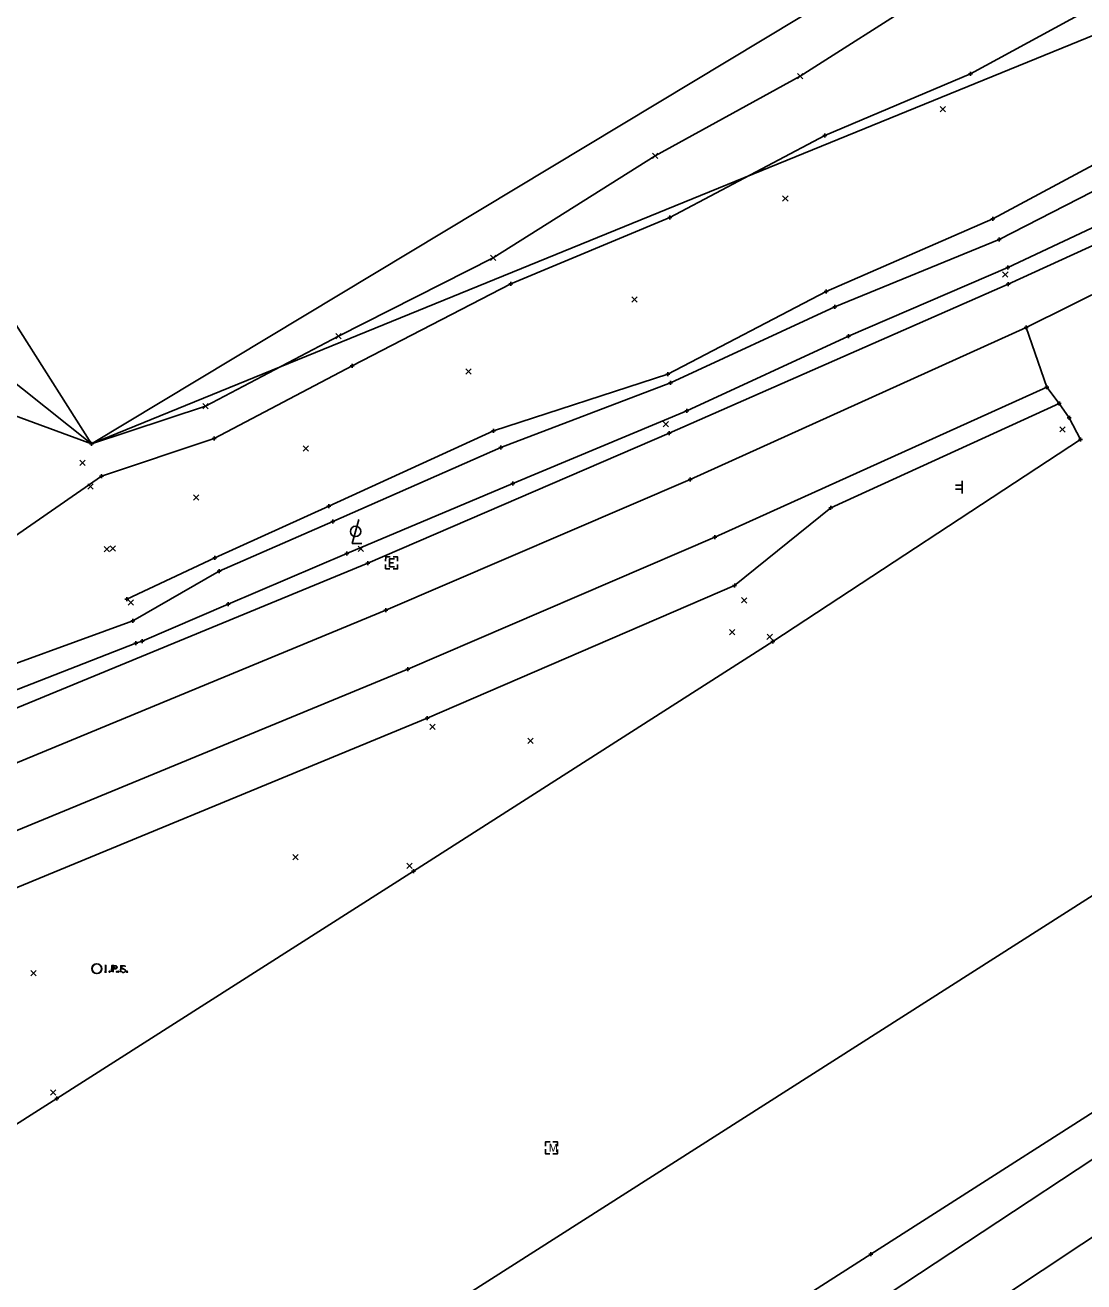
# Model space of a CAD drawing. Extents: x 142461 to 147261, y 511126 to 514697.
# Drawn here: x 145873.8 to 146138.4, y 513841.1 to 514155.2 of the extents above; entities that cross this region are included whole.
import ezdxf

# ---------------------------------------------------------------- set-up
doc = ezdxf.new("R2010")
doc.units = 0
for name, color, linetype in [('DR_X_Ditch', 7, 'Continuous'), ('DR_X_Storm_Sewer', 7, 'Continuous'), ('LT_X_Poles', 7, 'Continuous'), ('PM_X_Surveyed_Line', 7, 'Continuous'), ('PV_X_EOP', 7, 'Continuous'), ('RD_X_Fence', 7, 'Continuous'), ('SN_X_Public', 7, 'Continuous'), ('SV_P_Mon_Cells_Set', 7, 'Continuous'), ('SV_X_Mon_Cells_Found', 7, 'Continuous'), ('SV_X_Original_Ground', 7, 'Continuous'), ('SV_X_Random_Point', 7, 'Continuous'), ('SV_X_Shot_Marker', 7, 'Continuous'), ('SV_X_Toe_of_Slope', 7, 'Continuous'), ('SV_X_Top_of_Bank', 7, 'Continuous'), ('UT_X_Electric_Cells', 7, 'Continuous'), ('VG_X_Tree_Line_Lt', 7, 'Continuous')]:
    doc.layers.add(name, color=color, linetype=linetype)

msp = doc.modelspace()

# ---------------------------------------------------------------- linework, layer by layer
at = {"layer": 'DR_X_Ditch'}
msp.add_lwpolyline([(146157.06, 514121.98), (146117.23, 514101.58), (146076.19, 514084.75), (146035.13, 514065.78), (145992.71, 514049.65), (145950.73, 514031.13), (145922.3, 514018.72), (145900.71, 514006.31), (145857.21, 513990.47), (145797.53, 513968.82), (145752.93, 513945.88), (145703.51, 513927.11), (145660.81, 513900.76), (145647.2, 513892.42)], dxfattribs=at)
at = {"layer": 'DR_X_Storm_Sewer'}
msp.add_line((146183.01, 513964.68), (145764.65, 513697.97), dxfattribs=at)
at = {"layer": 'LT_X_Poles'}
msp.add_lwpolyline([(145957.21, 514031.59), (145955.57, 514025.62), (145957.94, 514025.59)], dxfattribs=at)
msp.add_circle((145956.39, 514028.64), 1.3, dxfattribs=at)
at = {"layer": 'PM_X_Surveyed_Line'}
for points in [[(146936.5, 514545.38), (146901.96, 514523.88), (146817.16, 514475.05), (146691.97, 514405.14), (146614.79, 514358.5), (146537.21, 514310.98), (146456.62, 514262.43), (146373.73, 514213.61), (146290.32, 514166.13), (146211.14, 514122.87), (146123.97, 514079.6), (146039.98, 514041.62), (145963.95, 514008.93), (145842.42, 513958.73), (145748.84, 513919.85), (145682.8, 513887.45), (145618.56, 513849.17)], [(145298.44, 513626.69), (145354.36, 513662.3), (145438.7, 513716.14), (145519.08, 513767.31), (145596.03, 513816.21), (145627.23, 513836.01), (145690.35, 513873.88), (145755.45, 513905.52), (145849.22, 513944.68), (145969.45, 513994.2), (146046.19, 514027.21), (146129.15, 514064.67)], [(145307.75, 513247.77), (145337.8, 513273.35), (145402.01, 513328.15), (145492.27, 513403.98), (145551.47, 513453.67), (145589.5, 513485), (145652.45, 513535.43), (145708.49, 513578.45), (145823.05, 513660.55), (145922.26, 513727.29), (146005.91, 513782.8), (146089.52, 513838.01), (146168.07, 513889.83), (146245.86, 513941.57), (146299.38, 513977.14)], [(145071.95, 513203.81), (145158.73, 513259.05), (145217.02, 513295.98), (145277.61, 513334.31), (145360.24, 513386.81), (145456.59, 513448.28), (145523.93, 513491.08), (145564.47, 513516.91), (145634.3, 513561.26), (145696.38, 513600.68), (145817.65, 513677.73), (145914.61, 513739.23), (145999.16, 513793.04), (146085.16, 513848.04), (146162.9, 513897.7)], [(145321.53, 513222.56), (145353.45, 513259.97), (145411.74, 513315.95), (145502.86, 513392.29), (145560.91, 513440.87), (145599.98, 513473.12), (145662.14, 513522.91), (145718.75, 513566.31), (145832.41, 513647.03), (145931.14, 513713.4), (146014.31, 513768.75), (146098.5, 513824.38), (146177.34, 513876.68)]]:
    msp.add_lwpolyline(points, dxfattribs=at)
at = {"layer": 'PV_X_EOP'}
for p, q in [((146207.13, 514130.54), (146119.47, 514090.47)), ((146119.47, 514090.47), (146034.79, 514053.23)), ((146034.79, 514053.23), (145959.48, 514020.69)), ((145959.48, 514020.69), (145837.72, 513970.53))]:
    msp.add_line(p, q, dxfattribs=at)
msp.add_lwpolyline([(145537.78, 513667.71), (145623.97, 513722.57), (145710.71, 513777.95), (145799.7, 513834.74), (145881.69, 513886.93), (145970.86, 513943.75), (146060.64, 514001.13), (146137.55, 514051.63), (146134.78, 514057.05), (146132.28, 514060.58), (146075.14, 514034.52), (146051.13, 514015.12), (145974.31, 513981.98), (145855.11, 513932.79), (145759.64, 513893.27), (145691.31, 513860.37), (145635.49, 513829), (145602.1, 513807.83)], dxfattribs=at)
at = {"layer": 'RD_X_Fence'}
msp.add_lwpolyline([(146900.86, 514646.23), (146332.42, 514316.7), (145890.39, 514050.56), (145774.93, 514232.06), (145655.09, 514421.49), (144949.64, 513970.2), (144936.36, 513451.75), (144101.94, 512896.99), (144046.01, 512862.62), (143758.01, 512670.87), (143619.22, 512579.24), (143474.12, 512483.15), (143357.83, 512406.57), (143315.36, 512377.21)], dxfattribs=at)
at = {"layer": 'SN_X_Public'}
for p, q in [((146107.97, 514041.3), (146107.97, 514038.1)), ((146107.97, 514040.18), (146106.37, 514040.18)), ((146107.97, 514039.22), (146106.37, 514039.22)), ((146107.97, 514039.7), (146107.97, 514039.7))]:
    msp.add_line(p, q, dxfattribs=at)
at = {"layer": 'SV_P_Mon_Cells_Set'}
for p, q in [((145893.73, 513918.51), (145894.13, 513918.51)), ((145893.74, 513920.11), (145894.14, 513920.11)), ((145893.93, 513918.51), (145893.94, 513920.11)), ((145895.78, 513919.33), (145896.42, 513919.32)), ((145898.77, 513919.11), (145898.04, 513919.5))]:
    msp.add_line(p, q, dxfattribs=at)
msp.add_lwpolyline([(145895.77, 513918.49), (145895.78, 513920.09), (145896.43, 513920.09)], dxfattribs=at)
for centre, radius in [((145891.74, 513919.34), 1.2), ((145894.89, 513918.61), 0.14), ((145896.73, 513918.59), 0.14), ((145899.3, 513918.56), 0.14)]:
    msp.add_circle(centre, radius, dxfattribs=at)
for points in [[(145896.42, 513919.32), (145896.49, 513919.33), (145896.67, 513919.43), (145896.74, 513919.61), (145896.75, 513919.7), (145896.75, 513919.7), (145896.75, 513919.7)], [(145896.43, 513920.09), (145896.56, 513920.05), (145896.7, 513919.94), (145896.75, 513919.8), (145896.75, 513919.7)], [(145898.04, 513919.5), (145897.83, 513919.71), (145898.03, 513919.97), (145898.03, 513919.97), (145898.03, 513919.97)], [(145898.76, 513918.58), (145898.23, 513918.29), (145897.91, 513918.68), (145897.91, 513918.68)], [(145898.03, 513919.97), (145898.41, 513920.14), (145898.84, 513919.96), (145898.84, 513919.96), (145898.84, 513919.96)], [(145898.76, 513918.58), (145898.96, 513918.82), (145898.77, 513919.11), (145898.77, 513919.11), (145898.77, 513919.11)]]:
    msp.add_open_spline(points, degree=2, dxfattribs=at)
at = {"layer": 'SV_X_Mon_Cells_Found'}
for points in [[(145893.66, 513918.55), (145894.02, 513918.55)], [(145893.68, 513920.15), (145894.03, 513920.15)], [(145893.84, 513918.55), (145893.86, 513920.15)], [(145894.8, 513918.75), (145894.86, 513918.75), (145894.89, 513918.73), (145894.92, 513918.68), (145894.92, 513918.61), (145894.89, 513918.56), (145894.85, 513918.54), (145894.8, 513918.54), (145894.77, 513918.56), (145894.73, 513918.62), (145894.74, 513918.68), (145894.77, 513918.73), (145894.8, 513918.75)], [(145895.41, 513918.53), (145895.42, 513920.13), (145895.95, 513920.13), (145896.01, 513920.11), (145896.08, 513920.09), (145896.12, 513920.06), (145896.15, 513920.04), (145896.19, 513919.97), (145896.23, 513919.91), (145896.25, 513919.81), (145896.24, 513919.66), (145896.23, 513919.61), (145896.21, 513919.53), (145896.17, 513919.44), (145896.12, 513919.41), (145896.09, 513919.38), (145896.03, 513919.36), (145895.94, 513919.35), (145895.41, 513919.35)], [(145897.05, 513918.73), (145897.11, 513918.73), (145897.14, 513918.7), (145897.17, 513918.65), (145897.17, 513918.59), (145897.14, 513918.54), (145897.1, 513918.52), (145897.05, 513918.52), (145897.02, 513918.54), (145896.98, 513918.59), (145896.98, 513918.66), (145897.02, 513918.71), (145897.05, 513918.73)], [(145898.43, 513920.1), (145897.67, 513920.11), (145897.65, 513918.51)], [(145897.66, 513919.33), (145898.2, 513919.32)], [(145899.2, 513918.71), (145899.25, 513918.71), (145899.29, 513918.68), (145899.32, 513918.63), (145899.32, 513918.57), (145899.29, 513918.52), (145899.25, 513918.49), (145899.2, 513918.49), (145899.16, 513918.52), (145899.13, 513918.57), (145899.13, 513918.63), (145899.17, 513918.68), (145899.2, 513918.71)], [(146004.96, 513873.1), (146003.83, 513873.11), (146003.85, 513874.23)], [(146003.85, 513874.99), (146003.86, 513876.11), (146004.99, 513876.1)], [(146006.85, 513874.2), (146006.84, 513873.08), (146005.69, 513873.09)], [(146005.72, 513876.09), (146006.87, 513876.08), (146006.85, 513874.96)]]:
    msp.add_lwpolyline(points, dxfattribs=at)
msp.add_circle((145891.66, 513919.37), 1.2, dxfattribs=at)
at = {"layer": 'SV_X_Original_Ground'}
for points in [[(146098.44, 514162.17), (146067.47, 514142.44), (146031.26, 514122.53), (145990.77, 514097.03), (145952.12, 514077.46), (145918.87, 514059.94), (145890.39, 514050.56), (145838.95, 514091.41), (145827.05, 514125.24), (145811.25, 514166.19)], [(144853.86, 513268.93), (144863.53, 513255.94), (144864.91, 513253.13), (144870.59, 513243.84), (144959.33, 513299.47), (145056.87, 513361.54), (145139.95, 513414.46), (145215.58, 513462.65), (145285.89, 513507.37), (145368.16, 513559.73), (145452.44, 513613.25), (145537.78, 513667.71), (145623.97, 513722.57), (145710.71, 513777.95), (145799.7, 513834.74), (145881.69, 513886.93), (145970.86, 513943.75), (146060.64, 514001.13), (146137.55, 514051.63), (146134.78, 514057.05), (146132.28, 514060.58), (146129.15, 514064.67), (146123.97, 514079.6), (146211.14, 514122.87)], [(146162.9, 513897.7), (146085.16, 513848.04), (145999.16, 513793.04), (145914.61, 513739.23), (145817.65, 513677.73), (145696.38, 513600.68), (145634.3, 513561.26), (145564.47, 513516.91), (145523.93, 513491.08), (145456.59, 513448.28), (145360.24, 513386.81), (145277.61, 513334.31), (145217.02, 513295.98), (145158.73, 513259.05), (145071.95, 513203.81)]]:
    msp.add_lwpolyline(points, dxfattribs=at)
at = {"layer": 'SV_X_Random_Point'}
for p, q in [((146066.8, 514141.77), (146068.14, 514143.11)), ((146066.8, 514143.11), (146068.14, 514141.77)), ((146102.53, 514133.53), (146103.86, 514134.87)), ((146102.53, 514134.87), (146103.86, 514133.53)), ((146030.59, 514121.86), (146031.92, 514123.2)), ((146030.59, 514123.2), (146031.92, 514121.86)), ((146063.13, 514111.17), (146064.47, 514112.51)), ((146063.13, 514112.51), (146064.47, 514111.17)), ((145990.1, 514096.36), (145991.43, 514097.7)), ((145990.1, 514097.7), (145991.43, 514096.36)), ((146118.11, 514092.18), (146119.46, 514093.5)), ((146118.12, 514093.51), (146119.44, 514092.16)), ((146025.44, 514085.92), (146026.77, 514087.26)), ((146025.44, 514087.26), (146026.77, 514085.92)), ((145951.45, 514076.79), (145952.79, 514078.12)), ((145951.45, 514078.12), (145952.79, 514076.79)), ((145983.98, 514067.92), (145985.31, 514069.26)), ((145983.98, 514069.26), (145985.31, 514067.92)), ((145918.21, 514059.27), (145919.54, 514060.61)), ((145918.21, 514060.61), (145919.54, 514059.27)), ((146033.25, 514054.8), (146034.6, 514056.12)), ((146033.27, 514056.14), (146034.59, 514054.79)), ((146132.38, 514053.49), (146133.73, 514054.81)), ((146132.39, 514054.82), (146133.71, 514053.47)), ((145943.32, 514048.66), (145944.65, 514050)), ((145943.32, 514050), (145944.65, 514048.66)), ((145887.49, 514045.15), (145888.83, 514046.49)), ((145887.49, 514046.49), (145888.83, 514045.15)), ((145889.43, 514039.18), (145890.76, 514040.52)), ((145889.43, 514040.52), (145890.76, 514039.18)), ((145915.89, 514036.46), (145917.23, 514037.79)), ((145915.89, 514037.79), (145917.23, 514036.46)), ((145893.56, 514023.5), (145894.89, 514024.84)), ((145893.56, 514024.84), (145894.89, 514023.5)), ((145895.03, 514023.68), (145896.36, 514025.02)), ((145895.03, 514025.02), (145896.36, 514023.68)), ((145956.99, 514023.64), (145958.34, 514024.96)), ((145957.01, 514024.97), (145958.33, 514023.63)), ((145899.53, 514010.2), (145900.86, 514011.53)), ((145899.53, 514011.53), (145900.86, 514010.2)), ((146052.84, 514010.76), (146054.18, 514012.08)), ((146052.85, 514012.09), (146054.17, 514010.74)), ((146049.83, 514002.76), (146051.17, 514004.09)), ((146049.83, 514004.09), (146051.17, 514002.76)), ((146059.21, 514001.66), (146060.56, 514002.98)), ((146059.23, 514002.99), (146060.55, 514001.64)), ((145974.91, 513979.14), (145976.26, 513980.47)), ((145974.93, 513980.48), (145976.25, 513979.13)), ((145999.45, 513975.63), (146000.79, 513976.96)), ((145999.45, 513976.96), (146000.79, 513975.63)), ((145940.72, 513946.59), (145942.05, 513947.93)), ((145940.72, 513947.93), (145942.05, 513946.59)), ((145969.18, 513944.42), (145970.53, 513945.74)), ((145969.2, 513945.75), (145970.52, 513944.41)), ((145875.23, 513917.55), (145876.57, 513918.89)), ((145875.23, 513918.89), (145876.57, 513917.55)), ((145880.11, 513887.77), (145881.45, 513889.09)), ((145880.12, 513889.11), (145881.44, 513887.76))]:
    msp.add_line(p, q, dxfattribs=at)
at = {"layer": 'SV_X_Shot_Marker'}
for p, q in [((146109.55, 514143.01), (146110.55, 514143.01)), ((146110.05, 514143.51), (146110.05, 514142.51)), ((146110.05, 514143.01), (146110.05, 514143.01)), ((146073.17, 514127.61), (146074.17, 514127.61)), ((146073.67, 514128.11), (146073.67, 514127.11)), ((146073.67, 514127.61), (146073.67, 514127.61)), ((146034.4, 514107.11), (146035.4, 514107.11)), ((146034.9, 514107.61), (146034.9, 514106.61)), ((146034.9, 514107.11), (146034.9, 514107.11)), ((146115.14, 514106.77), (146116.14, 514106.77)), ((146115.64, 514107.27), (146115.64, 514106.27)), ((146115.64, 514106.77), (146115.64, 514106.77)), ((146116.73, 514101.58), (146117.73, 514101.58)), ((146117.23, 514102.08), (146117.23, 514101.08)), ((146117.23, 514101.58), (146117.23, 514101.58)), ((146118.9, 514094.6), (146119.9, 514094.6)), ((146119.4, 514095.1), (146119.4, 514094.1)), ((146119.4, 514094.6), (146119.4, 514094.6)), ((145995.2, 514091.05), (145995.2, 514090.05)), ((146119.48, 514090.97), (146119.47, 514089.97)), ((145994.7, 514090.55), (145995.7, 514090.55)), ((145995.2, 514090.55), (145995.2, 514090.55)), ((146073.49, 514088.62), (146074.49, 514088.62)), ((146073.99, 514089.12), (146073.99, 514088.12)), ((146073.99, 514088.62), (146073.99, 514088.62)), ((146118.97, 514090.47), (146119.97, 514090.46)), ((146119.47, 514090.47), (146119.47, 514090.47)), ((146075.69, 514084.75), (146076.69, 514084.75)), ((146076.19, 514085.25), (146076.19, 514084.25)), ((146076.19, 514084.75), (146076.19, 514084.75)), ((146123.47, 514079.61), (146124.47, 514079.6)), ((146123.98, 514080.1), (146123.97, 514079.1)), ((146123.97, 514079.6), (146123.97, 514079.6)), ((146079.06, 514077.44), (146080.06, 514077.44)), ((146079.56, 514077.94), (146079.56, 514076.94)), ((146079.56, 514077.44), (146079.56, 514077.44)), ((145955.03, 514070.02), (145956.03, 514070.02)), ((145955.53, 514070.52), (145955.53, 514069.52)), ((145955.53, 514070.02), (145955.53, 514070.02)), ((146033.93, 514067.96), (146034.93, 514067.96)), ((146034.43, 514068.46), (146034.43, 514067.46)), ((146034.43, 514067.96), (146034.43, 514067.96)), ((146034.63, 514065.78), (146035.63, 514065.78)), ((146035.13, 514066.28), (146035.13, 514065.28)), ((146035.13, 514065.78), (146035.13, 514065.78)), ((146128.65, 514064.67), (146129.65, 514064.66)), ((146129.15, 514065.17), (146129.14, 514064.17)), ((146129.15, 514064.67), (146129.15, 514064.67)), ((146131.78, 514060.59), (146132.78, 514060.58)), ((146132.29, 514061.08), (146132.28, 514060.08)), ((146132.28, 514060.58), (146132.28, 514060.58)), ((146038.65, 514058.81), (146039.65, 514058.81)), ((146039.15, 514059.31), (146039.15, 514058.31)), ((146039.15, 514058.81), (146039.15, 514058.81)), ((146134.28, 514057.05), (146135.28, 514057.04)), ((146134.79, 514057.55), (146134.78, 514056.55)), ((146134.78, 514057.05), (146134.78, 514057.05)), ((145990.34, 514053.81), (145991.34, 514053.81)), ((145990.84, 514054.31), (145990.84, 514053.31)), ((145990.84, 514053.81), (145990.84, 514053.81)), ((146034.29, 514053.23), (146035.29, 514053.22)), ((146034.79, 514053.73), (146034.78, 514052.73)), ((146034.79, 514053.23), (146034.79, 514053.23)), ((145889.89, 514050.57), (145890.89, 514050.56)), ((145889.89, 514050.57), (145890.89, 514050.56)), ((145890.39, 514051.06), (145890.38, 514050.06)), ((145890.39, 514051.06), (145890.38, 514050.06)), ((145890.39, 514050.56), (145890.39, 514050.56)), ((145890.39, 514050.56), (145890.39, 514050.56)), ((145920.53, 514051.83), (145921.53, 514051.83)), ((145921.03, 514052.33), (145921.03, 514051.33)), ((145921.03, 514051.83), (145921.03, 514051.83)), ((145992.71, 514050.15), (145992.71, 514049.15)), ((146137.05, 514051.64), (146138.05, 514051.63)), ((146137.55, 514052.13), (146137.54, 514051.13)), ((146137.55, 514051.63), (146137.55, 514051.63)), ((145992.21, 514049.65), (145993.21, 514049.65)), ((145992.71, 514049.65), (145992.71, 514049.65)), ((145892.38, 514042.46), (145893.38, 514042.46)), ((145892.88, 514042.96), (145892.88, 514041.96)), ((145892.88, 514042.46), (145892.88, 514042.46)), ((145995.17, 514040.62), (145996.17, 514040.62)), ((145995.67, 514041.12), (145995.67, 514040.12)), ((145995.67, 514040.62), (145995.67, 514040.62)), ((146039.48, 514041.63), (146040.48, 514041.62)), ((146039.99, 514042.12), (146039.98, 514041.12)), ((146039.98, 514041.62), (146039.98, 514041.62)), ((145949.17, 514034.98), (145950.17, 514034.98)), ((145949.67, 514035.48), (145949.67, 514034.48)), ((145949.67, 514034.98), (145949.67, 514034.98)), ((146074.64, 514034.53), (146075.64, 514034.52)), ((146075.14, 514035.02), (146075.13, 514034.02)), ((146075.14, 514034.52), (146075.14, 514034.52)), ((145950.23, 514031.13), (145951.23, 514031.13)), ((145950.73, 514031.63), (145950.73, 514030.63)), ((145950.73, 514031.13), (145950.73, 514031.13)), ((146045.69, 514027.22), (146046.69, 514027.21)), ((146046.19, 514027.71), (146046.18, 514026.71)), ((146046.19, 514027.21), (146046.19, 514027.21)), ((145920.73, 514022.03), (145921.73, 514022.03)), ((145921.23, 514022.53), (145921.23, 514021.53)), ((145921.23, 514022.03), (145921.23, 514022.03)), ((145953.67, 514023.11), (145954.67, 514023.11)), ((145954.17, 514023.61), (145954.17, 514022.61)), ((145954.17, 514023.11), (145954.17, 514023.11)), ((145921.8, 514018.72), (145922.8, 514018.72)), ((145922.3, 514019.22), (145922.3, 514018.22)), ((145922.3, 514018.72), (145922.3, 514018.72)), ((145958.98, 514020.69), (145959.98, 514020.68)), ((145959.48, 514021.19), (145959.47, 514020.19)), ((145959.48, 514020.69), (145959.48, 514020.69)), ((146051.14, 514015.62), (146051.13, 514014.62)), ((146050.63, 514015.12), (146051.63, 514015.11)), ((146051.13, 514015.12), (146051.13, 514015.12)), ((145898.73, 514011.67), (145899.73, 514011.67)), ((145899.23, 514012.17), (145899.23, 514011.17)), ((145899.23, 514011.67), (145899.23, 514011.67)), ((145924.05, 514010.47), (145925.05, 514010.47)), ((145924.55, 514010.97), (145924.55, 514009.97)), ((145924.55, 514010.47), (145924.55, 514010.47)), ((145963.95, 514009.43), (145963.94, 514008.43)), ((145900.21, 514006.31), (145901.21, 514006.31)), ((145900.71, 514006.81), (145900.71, 514005.81)), ((145900.71, 514006.31), (145900.71, 514006.31)), ((145963.45, 514008.94), (145964.45, 514008.93)), ((145963.95, 514008.93), (145963.95, 514008.93)), ((145900.99, 514000.74), (145901.99, 514000.74)), ((145901.49, 514001.24), (145901.49, 514000.24)), ((145901.49, 514000.74), (145901.49, 514000.74)), ((145902.55, 514001.18), (145903.55, 514001.18)), ((145903.05, 514001.68), (145903.05, 514000.68)), ((145903.05, 514001.18), (145903.05, 514001.18)), ((146060.14, 514001.13), (146061.14, 514001.12)), ((146060.65, 514001.63), (146060.64, 514000.63)), ((146060.64, 514001.13), (146060.64, 514001.13)), ((145968.95, 513994.21), (145969.95, 513994.2)), ((145969.46, 513994.7), (145969.45, 513993.7)), ((145969.45, 513994.2), (145969.45, 513994.2)), ((145973.81, 513981.99), (145974.81, 513981.98)), ((145974.31, 513982.48), (145974.3, 513981.48)), ((145974.31, 513981.98), (145974.31, 513981.98)), ((145970.36, 513943.76), (145971.36, 513943.75)), ((145970.87, 513944.25), (145970.86, 513943.25)), ((145970.86, 513943.75), (145970.86, 513943.75)), ((145881.19, 513886.94), (145882.19, 513886.93)), ((145881.7, 513887.43), (145881.69, 513886.43)), ((145881.69, 513886.93), (145881.69, 513886.93)), ((146084.66, 513848.04), (146085.66, 513848.03)), ((146085.16, 513848.54), (146085.15, 513847.54)), ((146085.16, 513848.04), (146085.16, 513848.04))]:
    msp.add_line(p, q, dxfattribs=at)
at = {"layer": 'SV_X_Toe_of_Slope'}
msp.add_lwpolyline([(146154.66, 514127.64), (146115.64, 514106.77), (146073.99, 514088.62), (146034.43, 514067.96), (145990.84, 514053.81), (145949.67, 514034.98), (145921.23, 514022.03), (145899.23, 514011.67)], dxfattribs=at)
at = {"layer": 'SV_X_Top_of_Bank'}
for points in [[(145613.13, 513898.19), (145648.07, 513921.31), (145698.25, 513941.92), (145742.01, 513965.74), (145792.17, 513981.79), (145848.25, 514011.56), (145892.88, 514042.46), (145921.03, 514051.83), (145955.53, 514070.02), (145995.2, 514090.55), (146034.9, 514107.11), (146073.67, 514127.61), (146110.05, 514143.01), (146152.44, 514166.06)], [(146159.97, 514113.67), (146119.4, 514094.6), (146079.56, 514077.44), (146039.15, 514058.81), (145995.67, 514040.62), (145954.17, 514023.11), (145924.55, 514010.47), (145903.05, 514001.18), (145901.49, 514000.74), (145858.96, 513984.13), (145801.36, 513958.89), (145754.74, 513940.56), (145705.41, 513917.5), (145664.4, 513895.17)]]:
    msp.add_lwpolyline(points, dxfattribs=at)
at = {"layer": 'UT_X_Electric_Cells'}
for p, q in [((145964.89, 514020.8), (145965.89, 514020.79)), ((145965.39, 514020.8), (145965.39, 514020.8))]:
    msp.add_line(p, q, dxfattribs=at)
for points in [[(145965.01, 514022.3), (145963.91, 514022.31), (145963.89, 514021.21)], [(145966.15, 514021.79), (145964.9, 514021.8), (145964.88, 514019.8), (145966.13, 514019.79)], [(145966.89, 514021.18), (145966.9, 514022.28), (145965.81, 514022.29)], [(145963.89, 514020.41), (145963.87, 514019.31), (145964.97, 514019.3)], [(145965.77, 514019.29), (145966.87, 514019.28), (145966.89, 514020.38)]]:
    msp.add_lwpolyline(points, dxfattribs=at)
at = {"layer": 'VG_X_Tree_Line_Lt'}
msp.add_lwpolyline([(146192.98, 514174.02), (145890.39, 514050.56), (145820.33, 514076.28), (145669.69, 513957.87), (145655.5, 513980.4), (145649.86, 514002.66), (145653.86, 514020.34), (145663.54, 514053.75), (145672.37, 514092.66), (145666.87, 514133.05), (145659.07, 514167.49)], dxfattribs=at)

# ---------------------------------------------------------------- texts
at = {"layer": 'SV_X_Mon_Cells_Found'}
msp.add_text('M', height=2, rotation=359.4086, dxfattribs=at).set_placement((146004.67, 513873.6))

doc.saveas('drawing.dxf')
